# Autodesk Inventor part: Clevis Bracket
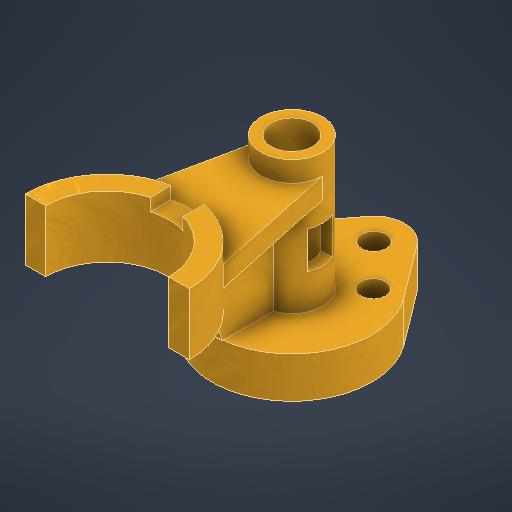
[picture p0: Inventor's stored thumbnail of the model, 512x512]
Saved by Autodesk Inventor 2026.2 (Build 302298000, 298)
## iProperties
Created: 2026-02
Part Number: Clevis Bracket
Material: Stainless Steel
Document SubType Name: Modeling
Designer: chuan
Density: 8 g/cm^3
Appearance: Weld - Brass
Author: chuan
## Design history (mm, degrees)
sketch "Sketch1"
  geometry: L1 (0, 0)-(19.799, -19.799); L2 (0, 0)-(28, 0); L3 (0, 0)-(-19.799, -19.799); L4 (31.2, -23.4)-(12, -49); L5 (-31.2, -23.4)-(-12, -49); C1 r 6 at (19.799, -19.799); C2 r 6 at (-19.799, -19.799); C3 r 6 at (0, -40); A1 r 39 centre (0, 0) between (31.2, -23.4) and (-31.2, -23.4); A2 r 15 centre (0, -40) between (12, -49) and (-12, -49); A3 r 28 centre (0, 0) between (-19.799, -19.799) and (19.799, -19.799); 1 further point
  constraints: 10 end point, 6 centre point, 6 point on circle, 5 coincident, 4 tangent, 2 equal radius, 1 equal length, 1 horizontal, 1 vertical alignment
  dimensions: "d0" = 78 diameter of A1; "d1" = 30 diameter of A2; "d2" = 40 distance of A2.centre point (0, 0); "d3" = 28 radius of A3; "d4" = 45 deg angle of L1 L2; "d5" = 90 deg angle of L3 L1; "d6" = 12 diameter of C2
extrude "Extrusion1" new body sketch "Sketch1" distance "d7" = 20; taper "d8" = 0 deg
sketch "Sketch2"
  geometry: C1 r 15 at (0, 0); C2 r 10 at (0, 0); 1 further point
  constraints: 2 centre point, 2 coincident
  dimensions: "d9" = 30 diameter of C1; "d10" = 20 diameter of C2
extrude "Extrusion2" join sketch "Sketch2" distance "d11" = 65; taper "d12" = 0 deg
sketch "Sketch3"
  geometry: L1 (0, 0)-(0, -90); L2 (-40, -90)-(-30, -90); L3 (30, -90)-(40, -90); A1 r 40 centre (0, -90) between (40, -90) and (-40, -90); A2 r 30 centre (0, -90) between (30, -90) and (-30, -90); 3 further points
  constraints: 6 end point, 4 point on circle, 2 centre point, 2 coincident, 2 horizontal, 2 horizontal alignment, 2 midpoint, 1 vertical, 1 vertical alignment
  dimensions: "d13" = 90 distance of L1.start L1.end; "d14" = 80 diameter of A1; "d15" = 60 diameter of A2
extrude "Extrusion3" join sketch "Sketch3" distance "d16" = 30; taper "d17" = 0 deg
sketch "Sketch4"
  geometry: L1 (0, 0)-(0, -90); L2 (-7.869, -61.05)-(-8.131, -50.835); L3 (7.869, -61.05)-(8.131, -50.835); A1 r 30 centre (0, -90) between (30, -90) and (-30, -90) reference; A2 r 40 centre (0, -90) between (40, -90) and (-40, -90) reference; 4 further points
  constraints: 6 end point, 2 midpoint, 2 point on circle, 2 symmetric about line, 1 vertical
  dimensions: "d18" = 16 distance of point (8, -55.943) point (-8, -55.943); "d19" = 10.21526 vertical distance of L3.start L3.end
extrude "Extrusion4" cut sketch "Sketch4" distance "d20" = 6; taper "d21" = 0 deg
sketch "Sketch5"
  geometry: L1 (55, 6)-(37, 6); L2 (37, 6)-(37, -6); L3 (37, -6)-(55, -6); L4 (55, -6)-(55, 6); L5 (85, 10)-(85, -10) reference; 1 further point
  constraints: 8 end point, 2 parallel, 1 horizontal, 1 perpendicular
  dimensions: "d22" = 18 distance of L3.end L2.end; "d23" = 12 distance of L2.end L1.end; "d24" = 30 distance between parallel lines of L5 L4; "d25" = 6 vertical distance of L2.end point (0, 0)
extrude "Extrusion5" cut sketch "Sketch5" extent not by distance; stored distance "d26" = 0; taper "d27" = 0 deg
workplane "Work Plane1"
sketch "Sketch6"
  geometry: L1 (0, 0)-(0, -60); L2 (-15, 0)-(-28.074, -61.507); L3 (15, 0)-(28.074, -61.507); C1 r 10 at (0, 0) reference; A1 r 15 centre (0, 0) between (-13.748, 6) and (-13.748, -6) reference; A2 r 40 centre (0, -90) between (28.074, -61.507) and (-28.074, -61.507); A3 r 15 centre (0, 0) between (-15, 0) and (15, 0); 2 further points
  constraints: 6 end point, 5 point on circle, 2 centre point, 2 symmetric about line, 1 concentric, 1 vertical
  dimensions: "d29" = 12 deg angle of L1 L2; "d30" = 40 radius of A2; "d31" = 15 radius of A3 (derived)
extrude "Extrusion6" join sketch "Sketch6" distance "d32" = 10; taper "d33" = 0 deg
sketch "Sketch7"
  geometry: L1 (0, -84)-(0, 119) reference; 1 further point
sketch "Sketch8"
  geometry: L1 (55, 90)-(55, 50) reference; L2 (20, -23.4)-(20, 39) reference; L3 (55, 50)-(20, 39); 1 further point
  constraints: 2 end point
feature "Rib1" sketch "Sketch8" dims "d34" = 1, "d35" = 10, "d36" = 0, "d37" = 0, "d38" = 1, "d39" = 1
body "Solid1"
